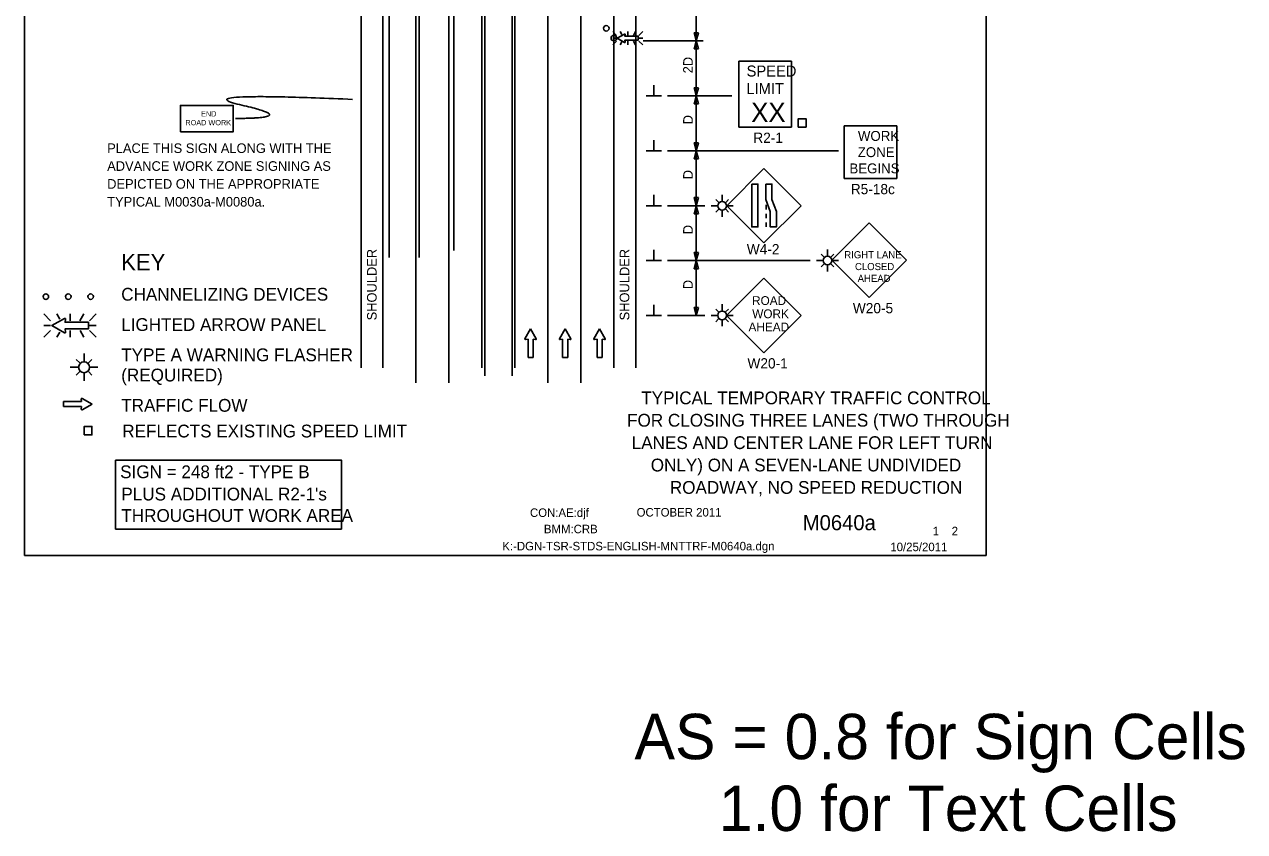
# Model space of a CAD drawing. Extents: x 16723 to 18475, y 7015 to 8267.
# Drawn here: x 16723 to 17611, y 7015 to 7603 of the extents above; entities that cross this region are included whole.
import ezdxf

# ---------------------------------------------------------------- set-up
doc = ezdxf.new("R2010")
doc.units = 0
for name, color, linetype in [('ALI_LEGAL_EX', 7, 'Continuous'), ('BORDER', 7, 'Continuous'), ('BORDER_SIGNAL_WO', 7, 'Continuous'), ('MT_SCRATCH_LEVEL_E', 7, 'Continuous'), ('PAVT_EDGE_EX', 7, 'Continuous'), ('TRAFFIC_SIGNS_PR', 7, 'Continuous'), ('TYPICAL_TEXT_DIMEN_EX', 7, 'Continuous'), ('TYPICAL_TEXT_DIMEN_PR', 7, 'Continuous')]:
    doc.layers.add(name, color=color, linetype=linetype)

msp = doc.modelspace()

# ---------------------------------------------------------------- linework, layer by layer
at = {"layer": 'ALI_LEGAL_EX'}
for p, q in [((17007.71, 7341.97), (17007.71, 8214.17)), ((17031.71, 7341.97), (17031.71, 8214.17)), ((17057.71, 7347.02), (17057.71, 8219.23)), ((17077.71, 7347.02), (17077.71, 8219.23)), ((17103.71, 7341.97), (17103.71, 8214.17)), ((17127.71, 7341.97), (17127.71, 8214.17))]:
    msp.add_line(p, q, dxfattribs=at)
for points in [[(17007.71, 7541.97), (17007.71, 7566.97)], [(17031.71, 7541.97), (17031.71, 7566.97)], [(17057.71, 7541.97), (17057.71, 7566.97)], [(17077.71, 7541.97), (17077.71, 7566.97)], [(17103.71, 7541.97), (17103.71, 7566.97)], [(17127.71, 7541.97), (17127.71, 7566.97)], [(17007.71, 7441.97), (17007.71, 7466.97)], [(17031.71, 7441.97), (17031.71, 7466.97)], [(17057.71, 7441.97), (17057.71, 7466.97)], [(17077.71, 7441.97), (17077.71, 7466.97)], [(17103.71, 7441.97), (17103.71, 7466.97)], [(17127.71, 7441.97), (17127.71, 7466.97)], [(17007.71, 7352.81), (17007.71, 7366.97)], [(17031.71, 7352.81), (17031.71, 7366.97)], [(17057.71, 7352.81), (17057.71, 7366.97)], [(17077.71, 7352.81), (17077.71, 7366.97)], [(17103.71, 7352.81), (17103.71, 7366.97)], [(17127.71, 7352.81), (17127.71, 7366.97)]]:
    msp.add_lwpolyline(points, dxfattribs=at)
at = {"layer": 'BORDER'}
for p, q in [((16722.75, 7216.25), (16722.75, 8216.25)), ((17422.75, 7216.25), (17422.75, 8216.25)), ((16722.75, 7216.25), (17422.75, 7216.25))]:
    msp.add_line(p, q, dxfattribs=at)
at = {"layer": 'MT_SCRATCH_LEVEL_E'}
for p, q in [((17091.15, 7381.27), (17087.04, 7374.03)), ((17091.15, 7381.27), (17087.04, 7374.03)), ((17095.3, 7374.03), (17091.15, 7381.27)), ((17095.3, 7374.03), (17091.15, 7381.27)), ((17116.24, 7381.27), (17112.13, 7374.03)), ((17116.24, 7381.27), (17112.13, 7374.03)), ((17120.39, 7374.03), (17116.24, 7381.27)), ((17120.39, 7374.03), (17116.24, 7381.27)), ((17141.33, 7381.27), (17137.22, 7374.03)), ((17141.33, 7381.27), (17137.22, 7374.03)), ((17145.47, 7374.03), (17141.33, 7381.27)), ((17145.47, 7374.03), (17141.33, 7381.27)), ((17087.52, 7373.35), (17089.3, 7373.66)), ((17087.52, 7373.35), (17089.3, 7373.66)), ((17089.3, 7373.66), (17089.3, 7360.41)), ((17089.3, 7373.66), (17089.3, 7360.41)), ((17093.04, 7360.41), (17093.04, 7373.66)), ((17093.04, 7373.66), (17094.82, 7373.35)), ((17093.04, 7360.41), (17093.04, 7373.66)), ((17093.04, 7373.66), (17094.82, 7373.35)), ((17112.61, 7373.35), (17114.39, 7373.66)), ((17112.61, 7373.35), (17114.39, 7373.66)), ((17114.39, 7373.66), (17114.39, 7360.41)), ((17114.39, 7373.66), (17114.39, 7360.41)), ((17118.13, 7360.41), (17118.13, 7373.66)), ((17118.13, 7373.66), (17119.91, 7373.35)), ((17118.13, 7360.41), (17118.13, 7373.66)), ((17118.13, 7373.66), (17119.91, 7373.35)), ((17137.7, 7373.35), (17139.48, 7373.66)), ((17137.7, 7373.35), (17139.48, 7373.66)), ((17139.48, 7373.66), (17139.48, 7360.41)), ((17139.48, 7373.66), (17139.48, 7360.41)), ((17143.22, 7360.41), (17143.22, 7373.66)), ((17143.22, 7373.66), (17145, 7373.35)), ((17143.22, 7360.41), (17143.22, 7373.66)), ((17143.22, 7373.66), (17145, 7373.35)), ((17089.3, 7360.41), (17093.04, 7360.41)), ((17089.3, 7360.41), (17093.04, 7360.41)), ((17114.39, 7360.41), (17118.13, 7360.41)), ((17114.39, 7360.41), (17118.13, 7360.41)), ((17139.48, 7360.41), (17143.22, 7360.41)), ((17139.48, 7360.41), (17143.22, 7360.41)), ((16764.39, 7328.36), (16751.13, 7328.36)), ((16751.13, 7328.36), (16751.13, 7324.61)), ((16764.39, 7328.36), (16751.13, 7328.36)), ((16751.13, 7328.36), (16751.13, 7324.61)), ((16764.07, 7330.13), (16764.39, 7328.36)), ((16764.07, 7330.13), (16764.39, 7328.36)), ((16771.99, 7326.5), (16764.75, 7330.61)), ((16771.99, 7326.5), (16764.75, 7330.61)), ((16764.75, 7322.36), (16771.99, 7326.5)), ((16764.75, 7322.36), (16771.99, 7326.5)), ((16751.13, 7324.61), (16764.39, 7324.61)), ((16751.13, 7324.61), (16764.39, 7324.61)), ((16764.39, 7324.61), (16764.07, 7322.84)), ((16764.39, 7324.61), (16764.07, 7322.84))]:
    msp.add_line(p, q, dxfattribs=at)
for centre, start, end in [((17087.45, 7373.81), 150.42484, 279.96381), ((17087.45, 7373.81), 150.42484, 279.96381), ((17094.89, 7373.81), 260.03619, 29.77312), ((17094.89, 7373.81), 260.03619, 29.77312), ((17112.54, 7373.81), 150.42484, 279.96381), ((17112.54, 7373.81), 150.42484, 279.96381), ((17119.98, 7373.81), 260.03619, 29.77312), ((17119.98, 7373.81), 260.03619, 29.77312), ((17137.63, 7373.81), 150.42484, 279.96381), ((17137.63, 7373.81), 150.42484, 279.96381), ((17145.07, 7373.81), 260.03619, 29.77312), ((17145.07, 7373.81), 260.03619, 29.77312), ((16764.53, 7330.21), 60.42484, 189.96381), ((16764.53, 7330.21), 60.42484, 189.96381), ((16764.53, 7322.77), 170.03619, 299.77312), ((16764.53, 7322.77), 170.03619, 299.77312)]:
    msp.add_arc(centre, 0.463, start, end, dxfattribs=at)
at = {"layer": 'PAVT_EDGE_EX'}
for p, q in [((17035.15, 8267.39), (17035.15, 7438.21)), ((16988.15, 8262.34), (16988.15, 7433.15)), ((17010.15, 8262.34), (17010.15, 7433.15)), ((16967.71, 8214.17), (16967.71, 7352.81)), ((16983.71, 8214.17), (16983.71, 7352.81)), ((17151.71, 8214.17), (17151.71, 7352.81)), ((17167.71, 8214.17), (17167.71, 7352.81)), ((17055.71, 7700.35), (17055.71, 7352.81)), ((17079.71, 7673.03), (17079.71, 7352.81))]:
    msp.add_line(p, q, dxfattribs=at)
at = {"layer": 'TRAFFIC_SIGNS_PR'}
for p, q in [((17150.9, 7597.59), (17153.72, 7594.77)), ((17153.72, 7592.74), (17150.9, 7592.74)), ((17156.34, 7597.59), (17157.54, 7595.5)), ((17161.81, 7594.77), (17161.81, 7597.59)), ((17167.59, 7597.59), (17165.97, 7594.77)), ((17169.89, 7594.77), (17172.71, 7597.59)), ((17169.89, 7592.74), (17172.71, 7592.74)), ((17150.9, 7587.89), (17153.72, 7590.71)), ((17157.62, 7590.07), (17156.36, 7587.89)), ((17161.81, 7590.71), (17161.81, 7587.89)), ((17165.94, 7590.71), (17167.57, 7587.89)), ((17169.89, 7590.71), (17172.71, 7587.89)), ((17242.56, 7576.01), (17280.96, 7576.01)), ((17242.56, 7528.01), (17242.56, 7576.01)), ((17280.96, 7528.01), (17280.96, 7576.01)), ((17242.56, 7528.01), (17280.96, 7528.01)), ((17319.34, 7490.65), (17319.34, 7529.05)), ((17319.34, 7529.05), (17357.74, 7529.05)), ((17357.74, 7490.65), (17357.74, 7529.05)), ((17260.99, 7498.01), (17233.83, 7470.86)), ((17288.14, 7470.86), (17260.99, 7498.01)), ((17319.34, 7490.65), (17357.74, 7490.65)), ((17230.61, 7474.27), (17230.61, 7478.77)), ((17227.46, 7470.72), (17222.63, 7470.72)), ((17228.1, 7473.23), (17226, 7475.34)), ((17228.1, 7468.21), (17226, 7466.11)), ((17233.12, 7473.23), (17235.23, 7475.34)), ((17233.12, 7468.21), (17235.23, 7466.11)), ((17233.76, 7470.72), (17238.64, 7470.72)), ((17233.83, 7470.86), (17260.99, 7443.71)), ((17260.99, 7443.71), (17288.14, 7470.86)), ((17262.63, 7471.35), (17262.63, 7468.15)), ((17230.61, 7462.77), (17230.61, 7467.17)), ((17262.63, 7464.95), (17262.63, 7461.75)), ((17262.63, 7458.55), (17262.63, 7455.35)), ((17337.49, 7458.31), (17310.34, 7431.16)), ((17364.64, 7431.16), (17337.49, 7458.31)), ((17304.67, 7433.48), (17302.56, 7435.59)), ((17307.18, 7434.52), (17307.18, 7439.02)), ((17309.7, 7433.48), (17311.8, 7435.59)), ((17304.03, 7430.97), (17299.19, 7430.97)), ((17304.67, 7428.45), (17302.56, 7426.35)), ((17307.18, 7423), (17307.18, 7427.41)), ((17309.7, 7428.45), (17311.8, 7426.35)), ((17310.34, 7431.16), (17337.49, 7404)), ((17310.34, 7430.97), (17315.22, 7430.97)), ((17337.49, 7404), (17364.64, 7431.16)), ((17260.79, 7418.21), (17233.61, 7391.03)), ((17287.98, 7391.03), (17260.79, 7418.21)), ((17230.45, 7394.58), (17230.45, 7399.08)), ((16736.88, 7392.06), (16741.81, 7387.13)), ((16748.64, 7388.24), (16746.44, 7392.06)), ((16755.96, 7387.13), (16755.96, 7392.06)), ((16763.2, 7387.13), (16766.05, 7392.06)), ((16770.11, 7387.13), (16775.05, 7392.06)), ((17227.3, 7391.03), (17222.46, 7391.03)), ((17227.94, 7393.54), (17225.83, 7395.65)), ((17227.94, 7388.52), (17225.83, 7386.41)), ((17232.97, 7393.54), (17235.07, 7395.65)), ((17232.97, 7388.52), (17235.07, 7386.41)), ((17233.61, 7391.03), (17238.49, 7391.03)), ((17233.61, 7391.03), (17260.79, 7363.84)), ((17260.79, 7363.84), (17287.98, 7391.03)), ((16741.81, 7383.57), (16736.88, 7383.57)), ((16736.88, 7375.08), (16741.81, 7380.01)), ((16755.96, 7380.01), (16755.96, 7375.08)), ((16766.09, 7375.08), (16763.24, 7380.01)), ((16770.11, 7383.57), (16775.05, 7383.57)), ((16770.11, 7380.01), (16775.05, 7375.08)), ((17230.45, 7383.06), (17230.45, 7387.47)), ((16746.39, 7375.08), (16748.51, 7378.74)), ((16766.15, 7357.66), (16766.15, 7363.28)), ((16762.21, 7353.22), (16756.17, 7353.22)), ((16763.01, 7356.36), (16760.38, 7358.99)), ((16769.28, 7356.36), (16771.91, 7358.99)), ((16770.08, 7353.22), (16776.18, 7353.22)), ((16763.01, 7350.08), (16760.38, 7347.45)), ((16766.15, 7343.27), (16766.15, 7348.78)), ((16769.28, 7350.08), (16771.91, 7347.45))]:
    msp.add_line(p, q, dxfattribs=at)
for points in [[(17159.48, 7589.73), (17154.17, 7592.74), (17159.48, 7595.78)], [(17159.98, 7595.42), (17159.75, 7594.13), (17169.47, 7594.13), (17169.47, 7591.38), (17159.75, 7591.38), (17159.98, 7590.08)], [(16751.89, 7388.85), (16742.6, 7383.57), (16751.89, 7378.25)], [(16752.77, 7378.88), (16752.37, 7381.14), (16769.38, 7381.14), (16769.38, 7385.95), (16752.37, 7385.95), (16752.77, 7388.23)]]:
    msp.add_lwpolyline(points, dxfattribs=at)
for points in [[(16836.32, 7524.64), (16874.72, 7524.64), (16874.72, 7543.84), (16836.32, 7543.84)], [(17285.97, 7528.01), (17291.57, 7528.01), (17291.57, 7534.18), (17285.97, 7534.18)], [(17252.09, 7486.6), (17252.09, 7455.35), (17256.58, 7455.35), (17256.58, 7486.6)], [(17262.23, 7486.6), (17262.23, 7475.42), (17265.57, 7466.53), (17265.57, 7455.35), (17270.06, 7455.35), (17270.06, 7466.53), (17266.72, 7475.42), (17266.72, 7486.6)], [(16766.25, 7304), (16771.84, 7304), (16771.84, 7310.17), (16766.25, 7310.17)]]:
    msp.add_lwpolyline(points, close=True, dxfattribs=at)
for centre, radius in [((17146.2, 7599.97), 2), ((17151.7, 7592.85), 2), ((17230.61, 7470.72), 3.15), ((17307.18, 7430.97), 3.15), ((16738.37, 7404.66), 2), ((16754.67, 7404.66), 2), ((16770.97, 7404.66), 2), ((17230.45, 7391.03), 3.15), ((16766.15, 7353.22), 3.94)]:
    msp.add_circle(centre, radius, dxfattribs=at)
for centre, radius, start, end in [((17159.64, 7595.48), 0.341, 350.04067, 118.51671), ((17159.64, 7590.02), 0.341, 241.10835, 9.26922), ((16752.18, 7388.32), 0.598, 350.73078, 118.89165), ((16752.18, 7378.77), 0.597, 241.48329, 9.95933)]:
    msp.add_arc(centre, radius, start, end, dxfattribs=at)
msp.add_open_spline([(16876.26, 7534.36), (16923.5, 7534.36), (16838.48, 7553.71), (16961.57, 7548.22)], degree=2, dxfattribs=at)
at = {"layer": 'TYPICAL_TEXT_DIMEN_EX'}
msp.add_lwpolyline([(16789.09, 7285.63), (16953.47, 7285.63), (16953.47, 7235.51), (16789.09, 7235.51)], close=True, dxfattribs=at)
at = {"layer": 'TYPICAL_TEXT_DIMEN_PR'}
for p, q in [((17211.71, 7590.85), (17211.71, 7621.36)), ((17211.71, 7590.85), (17210.14, 7596.71)), ((17210.14, 7596.71), (17211.71, 7596.71)), ((17211.71, 7596.71), (17213.28, 7596.71)), ((17213.28, 7596.71), (17211.71, 7590.85)), ((17216.71, 7590.85), (17173.15, 7590.85)), ((17210.14, 7584.99), (17211.71, 7590.85)), ((17211.71, 7584.99), (17210.14, 7584.99)), ((17211.71, 7590.85), (17213.28, 7584.99)), ((17211.71, 7590.85), (17211.71, 7550.85)), ((17213.28, 7584.99), (17211.71, 7584.99)), ((17180.84, 7550.85), (17180.84, 7558.63)), ((17186.46, 7550.85), (17175.21, 7550.85)), ((17190.71, 7550.85), (17237.67, 7550.85)), ((17211.71, 7550.85), (17210.14, 7556.71)), ((17210.14, 7556.71), (17211.71, 7556.71)), ((17210.14, 7544.99), (17211.71, 7550.85)), ((17211.71, 7556.71), (17213.28, 7556.71)), ((17213.28, 7556.71), (17211.71, 7550.85)), ((17211.71, 7550.85), (17213.28, 7544.99)), ((17211.71, 7550.85), (17211.71, 7510.85)), ((17211.71, 7544.99), (17210.14, 7544.99)), ((17213.28, 7544.99), (17211.71, 7544.99)), ((17180.84, 7510.85), (17180.84, 7518.63)), ((17211.71, 7510.85), (17210.14, 7516.71)), ((17210.14, 7516.71), (17211.71, 7516.71)), ((17211.71, 7516.71), (17213.28, 7516.71)), ((17213.28, 7516.71), (17211.71, 7510.85)), ((17186.46, 7510.85), (17175.21, 7510.85)), ((17315.18, 7510.85), (17190.71, 7510.85)), ((17210.14, 7504.99), (17211.71, 7510.85)), ((17211.71, 7504.99), (17210.14, 7504.99)), ((17211.71, 7510.85), (17213.28, 7504.99)), ((17211.71, 7510.85), (17211.71, 7470.85)), ((17213.28, 7504.99), (17211.71, 7504.99)), ((17180.84, 7470.85), (17180.84, 7478.63)), ((17186.46, 7470.85), (17175.21, 7470.85)), ((17190.71, 7470.85), (17217.82, 7470.85)), ((17211.71, 7470.85), (17210.14, 7476.71)), ((17210.14, 7476.71), (17211.71, 7476.71)), ((17210.14, 7464.99), (17211.71, 7470.85)), ((17211.71, 7476.71), (17213.28, 7476.71)), ((17213.28, 7476.71), (17211.71, 7470.85)), ((17211.71, 7470.85), (17213.28, 7464.99)), ((17211.71, 7470.85), (17211.71, 7430.85)), ((17211.71, 7464.99), (17210.14, 7464.99)), ((17213.28, 7464.99), (17211.71, 7464.99)), ((17180.84, 7430.85), (17180.84, 7438.63)), ((17211.71, 7430.85), (17210.14, 7436.71)), ((17210.14, 7436.71), (17211.71, 7436.71)), ((17211.71, 7436.71), (17213.28, 7436.71)), ((17213.28, 7436.71), (17211.71, 7430.85)), ((17186.46, 7430.85), (17175.21, 7430.85)), ((17294.56, 7430.85), (17190.71, 7430.85)), ((17210.14, 7424.99), (17211.71, 7430.85)), ((17211.71, 7424.99), (17210.14, 7424.99)), ((17211.71, 7430.85), (17213.28, 7424.99)), ((17211.71, 7430.85), (17211.71, 7390.85)), ((17213.28, 7424.99), (17211.71, 7424.99)), ((17180.84, 7390.85), (17180.84, 7398.63)), ((17186.46, 7390.85), (17175.21, 7390.85)), ((17190.71, 7390.85), (17217.82, 7390.85)), ((17211.71, 7390.85), (17210.14, 7396.71)), ((17210.14, 7396.71), (17211.71, 7396.71)), ((17211.71, 7396.71), (17213.28, 7396.71)), ((17213.28, 7396.71), (17211.71, 7390.85))]:
    msp.add_line(p, q, dxfattribs=at)

# ---------------------------------------------------------------- texts
at = {"layer": 'BORDER'}
for s, p in [('TYPICAL TEMPORARY TRAFFIC CONTROL', (17171.67, 7326.32)), ('FOR CLOSING THREE LANES (TWO THROUGH', (17161.36, 7310.02)), ('LANES AND CENTER LANE FOR LEFT TURN', (17164.72, 7293.72)), ('ONLY) ON A SEVEN-LANE UNDIVIDED', (17178.56, 7277.42)), ('ROADWAY, NO SPEED REDUCTION', (17192.48, 7261.12))]:
    msp.add_text(s, height=9.3, dxfattribs=at).set_placement(p)
at = {"layer": 'BORDER_SIGNAL_WO'}
for s, height, p in [('CON:AE:djf', 6.2, (17090.69, 7244.31)), ('    OCTOBER 2011    ', 6.2, (17159.08, 7244.59)), ('BMM:CRB   ', 6.2, (17100.81, 7232.42)), ('    M0640a   ', 11, (17272.86, 7234.63)), (' 1    2 ', 6.2, (17381.45, 7230.95)), ('K:-DGN-TSR-STDS-ENGLISH-MNTTRF-M0640a.dgn         ', 6.2, (17070.55, 7219.96)), ('10/25/2011    ', 6.2, (17352.93, 7219.38)), ('AS = 0.8 for Sign Cells', 33.0301, (17166.75, 7067.97)), ('     1.0 for Text Cells', 33.0301, (17166.75, 7015.74))]:
    msp.add_text(s, height=height, dxfattribs=at).set_placement(p)
at = {"layer": 'TRAFFIC_SIGNS_PR'}
for s, height, p in [('SPEED', 8, (17248.32, 7564.87)), ('LIMIT', 8, (17248.16, 7552.07)), ('END', 3.831, (16851.32, 7535.77)), ('XX', 14.031, (17251.67, 7531.77)), ('ROAD WORK', 3.831, (16839.93, 7529.39)), ('R2-1', 7.44, (17253.23, 7516.57)), ('WORK', 7.217, (17329.34, 7518.01)), ('PLACE THIS SIGN ALONG WITH THE', 7, (16782.99, 7509.2)), ('ZONE', 7.217, (17329.22, 7506.2)), ('ADVANCE WORK ZONE SIGNING AS', 7, (16782.99, 7496.2)), ('BEGINS', 7.217, (17323.15, 7494.39)), ('DEPICTED ON THE APPROPRIATE', 7, (16782.99, 7483.2)), ('R5-18c', 7.44, (17324.15, 7479.21)), ('TYPICAL M0030a-M0080a.', 7, (16782.99, 7470.2)), ('W4-2', 7.44, (17248.48, 7435.46)), ('RIGHT LANE', 5.2, (17319.41, 7432.55)), ('CLOSED', 5.2, (17327.2, 7423.95)), ('AHEAD', 5.2, (17329.15, 7415.35)), ('ROAD', 6.408, (17252.32, 7398.57)), ('W20-5', 7.44, (17325.66, 7392.56)), ('WORK', 6.408, (17252.43, 7388.96)), ('AHEAD', 6.408, (17249.74, 7379.35)), ('W20-1', 7.449, (17248.95, 7352.39))]:
    msp.add_text(s, height=height, dxfattribs=at).set_placement(p)
at = {"layer": 'TYPICAL_TEXT_DIMEN_EX'}
for s, height, p in [('KEY', 12, (16793.21, 7423.77)), ('CHANNELIZING DEVICES', 9.3, (16793.21, 7401.72)), ('LIGHTED ARROW PANEL', 9.3, (16793.21, 7379.67)), ('TYPE A WARNING FLASHER', 9.3, (16793.21, 7357.62)), ('(REQUIRED)', 9.3, (16793.21, 7342.92)), ('TRAFFIC FLOW', 9.3, (16793.21, 7320.87)), ('REFLECTS EXISTING SPEED LIMIT', 9.3, (16793.97, 7302.17)), ('SIGN = 248 ft2 - TYPE B', 9.3, (16792.43, 7272.51)), ("PLUS ADDITIONAL R2-1's", 9.3, (16793.31, 7256.3)), ('THROUGHOUT WORK AREA', 9.3, (16793.31, 7240.7))]:
    msp.add_text(s, height=height, dxfattribs=at).set_placement(p)
at = {"layer": 'TYPICAL_TEXT_DIMEN_PR'}
for s, p in [('2D', (17209.15, 7567.19)), ('D', (17209.15, 7530.07)), ('D', (17209.15, 7490.07)), ('D', (17209.15, 7450.07)), ('SHOULDER', (16979.09, 7387.38)), ('SHOULDER', (17162.99, 7387.38)), ('D', (17209.15, 7410.07))]:
    msp.add_text(s, height=7, rotation=90, dxfattribs=at).set_placement(p)

doc.saveas('drawing.dxf')
